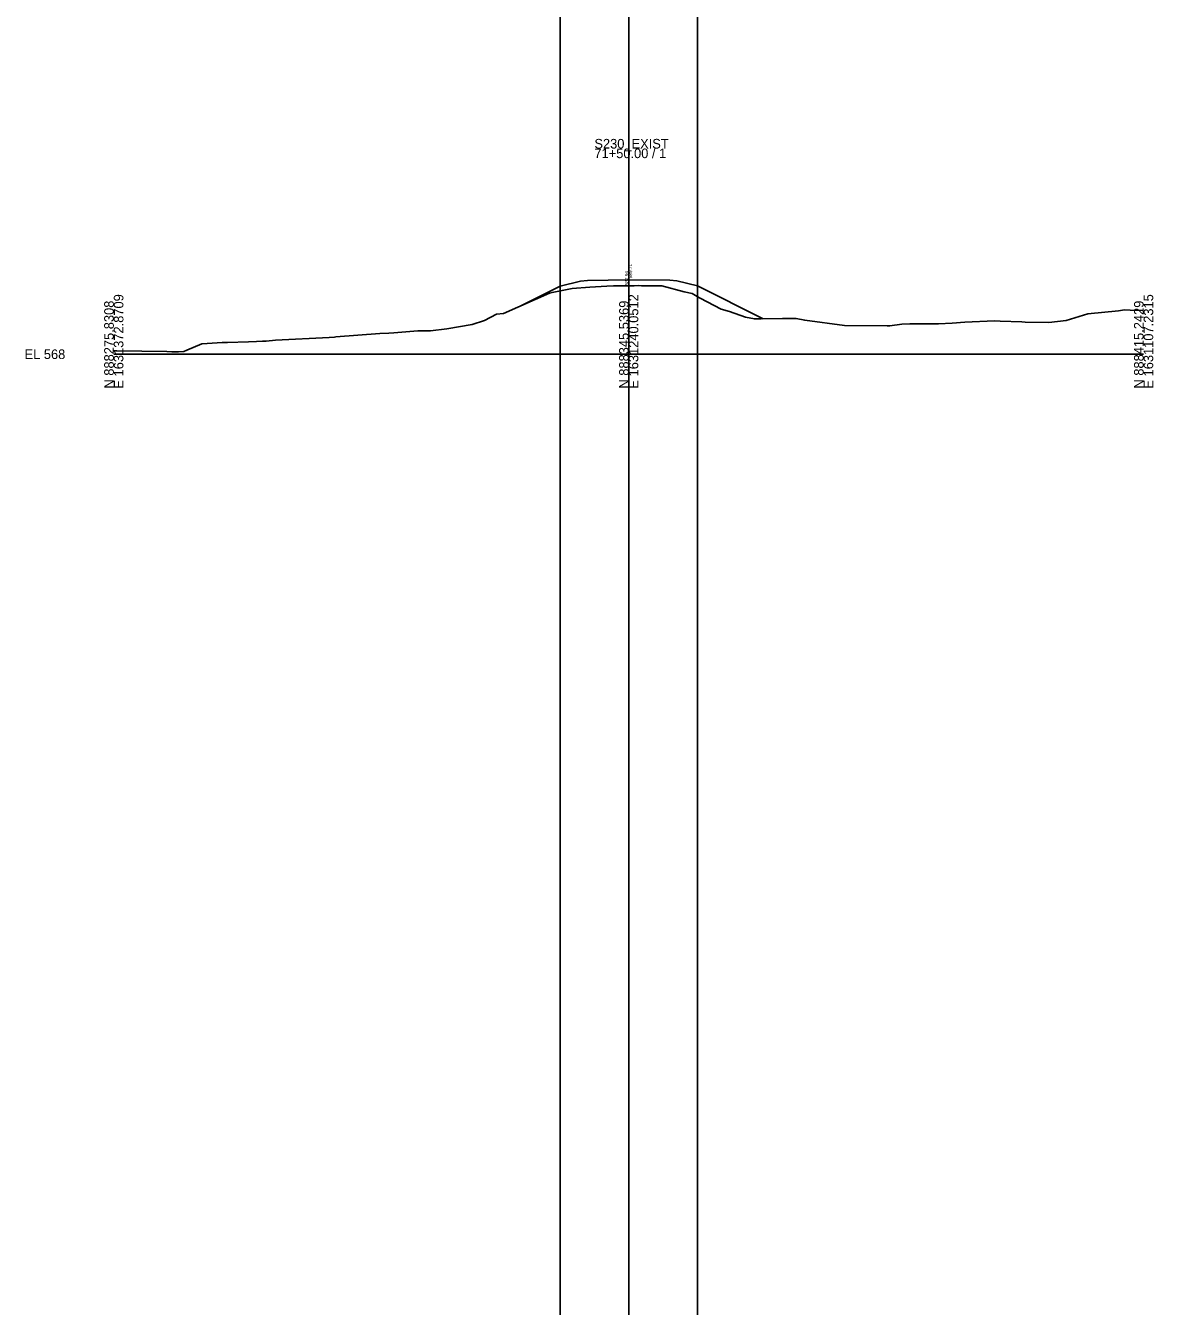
# Model space of a CAD drawing. Extents: x 1631115 to 1631443, y 885974 to 892071.
# Drawn here: x 1631114.8 to 1631443.3, y 890206.3 to 890579.4 of the extents above; entities that cross this region are included whole.
import ezdxf

# ---------------------------------------------------------------- set-up
doc = ezdxf.new("R2010")
doc.units = 0
for name, color, linetype in [('Default', 7, 'Continuous'), ('RD_GPK_XS_Cell', 7, 'Continuous'), ('RD_XS_EarthShd', 7, 'Continuous'), ('RD_XS_ExGround', 7, 'Continuous'), ('RD_XS_Pave', 7, 'Continuous'), ('RD_XS_TieSlope', 7, 'Continuous'), ('RD_XS_TX_Elev_EX', 7, 'Continuous'), ('RD_XS_TX_Elev_PR', 7, 'Continuous')]:
    doc.layers.add(name, color=color, linetype=linetype)

msp = doc.modelspace()

# ---------------------------------------------------------------- linework, layer by layer
at = {"layer": 'Default'}
for p, q in [((1631270.47, 885983.65), (1631270.47, 892068.63)), ((1631290.47, 885983.65), (1631290.47, 892068.63)), ((1631310.47, 885983.65), (1631310.47, 892068.63))]:
    msp.add_line(p, q, dxfattribs=at)
at = {"layer": 'RD_GPK_XS_Cell'}
for p, q in [((1631290.47, 890483.65), (1631290.47, 890543.56)), ((1631140.47, 890483.65), (1631290.47, 890483.65)), ((1631290.47, 890483.65), (1631440.47, 890483.65))]:
    msp.add_line(p, q, dxfattribs=at)
at = {"layer": 'RD_XS_EarthShd'}
for p, q in [((1631278.47, 890505.12), (1631276.47, 890504.96)), ((1631302.47, 890505.2), (1631304.47, 890505.04))]:
    msp.add_line(p, q, dxfattribs=at)
at = {"layer": 'RD_XS_ExGround'}
msp.add_lwpolyline([(1631140.47, 890484.72), (1631141.35, 890484.63), (1631155.94, 890484.4), (1631157.41, 890484.35), (1631159.35, 890484.36), (1631160.86, 890484.42), (1631161.75, 890484.79), (1631166.14, 890486.66), (1631167.71, 890486.8), (1631172.05, 890487.05), (1631173.57, 890487.03), (1631179.73, 890487.23), (1631182.04, 890487.35), (1631183.81, 890487.41), (1631184.9, 890487.47), (1631187.59, 890487.73), (1631203.22, 890488.57), (1631204.77, 890488.66), (1631205.2, 890488.69), (1631218, 890489.73), (1631220.6, 890489.75), (1631222.09, 890489.85), (1631229.08, 890490.5), (1631232.73, 890490.46), (1631237.44, 890491.05), (1631244.91, 890492.3), (1631248.42, 890493.48), (1631251.95, 890495.3), (1631253.96, 890495.55), (1631267.42, 890501.41), (1631268.18, 890501.66), (1631273.95, 890502.77), (1631279.1, 890503.18), (1631284.05, 890503.45), (1631286.08, 890503.55), (1631290.47, 890503.59), (1631292.08, 890503.6), (1631293.2, 890503.62), (1631294.17, 890503.61), (1631299.66, 890503.61), (1631300.12, 890503.57), (1631306.63, 890501.82), (1631308.96, 890501.29), (1631310.41, 890500.51), (1631311.25, 890500.02), (1631317.4, 890496.82), (1631319.79, 890496.12), (1631324.52, 890494.4), (1631327.11, 890493.95), (1631329.04, 890493.92), (1631335.24, 890494.02), (1631337.88, 890494.02), (1631339.28, 890494.05), (1631341.76, 890493.54), (1631353.3, 890491.97), (1631365.73, 890491.96), (1631366.51, 890491.95), (1631370.04, 890492.41), (1631372.39, 890492.46), (1631380.69, 890492.52), (1631384.72, 890492.71), (1631388.41, 890493), (1631396.99, 890493.35), (1631398.7, 890493.3), (1631405.03, 890493.04), (1631406, 890493.03), (1631412.83, 890492.93), (1631417.89, 890493.45), (1631424.17, 890495.41), (1631433.18, 890496.31), (1631434.94, 890496.61), (1631436.52, 890496.51), (1631440.47, 890496.35)], dxfattribs=at)
at = {"layer": 'RD_XS_Pave'}
for p, q in [((1631278.47, 890505.12), (1631290.47, 890505.36)), ((1631290.47, 890505.36), (1631302.47, 890505.2))]:
    msp.add_line(p, q, dxfattribs=at)
at = {"layer": 'RD_XS_TieSlope'}
for p, q in [((1631270.47, 890503.46), (1631259.28, 890497.87)), ((1631276.47, 890504.96), (1631270.47, 890503.46)), ((1631304.47, 890505.04), (1631310.47, 890503.54)), ((1631310.47, 890503.54), (1631329.68, 890493.93))]:
    msp.add_line(p, q, dxfattribs=at)

# ---------------------------------------------------------------- texts
at = {"layer": 'RD_GPK_XS_Cell'}
for s, p in [('S230_EXIST', (1631280.47, 890543.56)), ('71+50.00 / 1', (1631280.47, 890540.76)), ('EL 568', (1631114.47, 890482.25))]:
    msp.add_text(s, height=2.8, dxfattribs=at).set_placement(p)
for s, p in [('N 888275.8308', (1631140.47, 890473.65)), ('E 1631372.8709', (1631143.27, 890473.65)), ('N 888345.5369', (1631290.47, 890473.65)), ('E 1631240.0512', (1631293.27, 890473.65)), ('N 888415.2429', (1631440.47, 890473.65)), ('E 1631107.2315', (1631443.27, 890473.65))]:
    msp.add_text(s, height=2.8, rotation=90, dxfattribs=at).set_placement(p)
at = {"layer": 'RD_XS_TX_Elev_EX'}
msp.add_text('587.94', height=1, rotation=90, dxfattribs=at).set_placement((1631290.37, 890503.69))
at = {"layer": 'RD_XS_TX_Elev_PR'}
msp.add_text(' 589.71', height=1, rotation=90, dxfattribs=at).set_placement((1631291.47, 890505.36))

doc.saveas('drawing.dxf')
